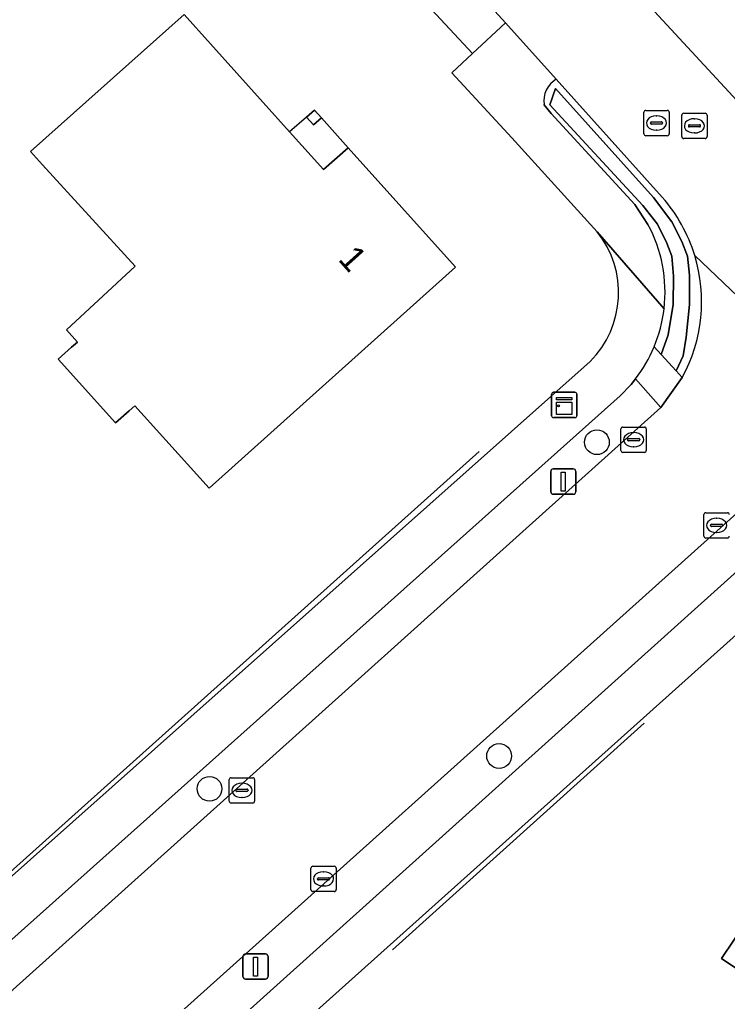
# Model space of a CAD drawing. Extents: x 163266 to 164362, y 381528 to 382286.
# Drawn here: x 163972.57 to 164000.54, y 381715.24 to 381754.03 of the extents above; entities that cross this region are included whole.
import ezdxf

# ---------------------------------------------------------------- set-up
doc = ezdxf.new("R2010")
doc.units = 0
for name, color, linetype in [('IMGEO_Boom', 7, 'Continuous'), ('IMGEO_Erf', 7, 'Continuous'), ('IMGEO_Groenvoorziening', 7, 'Continuous'), ('IMGEO_Haag', 7, 'Continuous'), ('IMGEO_Hek', 7, 'Continuous'), ('IMGEO_Kast', 7, 'Continuous'), ('IMGEO_Kolk', 7, 'Continuous'), ('IMGEO_Lichtmast', 7, 'Continuous'), ('IMGEO_Pand', 7, 'Continuous'), ('IMGEO_Pand_nummerreeks', 7, 'Continuous'), ('IMGEO_Pand_overbouw', 7, 'Continuous'), ('IMGEO_Rijbaan_lokaal_open', 7, 'Continuous'), ('IMGEO_Rioolput', 7, 'Continuous'), ('IMGEO_Voetpad_halfverhard', 7, 'Continuous'), ('IMGEO_Voetpad_open', 7, 'Continuous')]:
    doc.layers.add(name, color=color, linetype=linetype)

msp = doc.modelspace()

# ---------------------------------------------------------------- linework, layer by layer
at = {"layer": 'IMGEO_Boom'}
for centre in [(163995.384, 381737.33), (163991.517, 381724.931), (163980.071, 381723.636)]:
    msp.add_circle(centre, 0.489, dxfattribs=at)
at = {"layer": 'IMGEO_Erf'}
for points in [[(163995.387, 381745.649), (163992.019, 381749.355), (163989.649, 381751.925), (163990.472, 381752.694), (163988.491, 381754.827), (163984.719, 381759.012), (163982.069, 381761.923), (163978.56, 381765.822), (163974.277, 381770.593), (163973.349, 381771.686), (163967.885, 381777.728), (163964.295, 381781.762), (163960.808, 381785.63), (163959.925, 381786.632), (163952.554, 381794.921), (163948.897, 381798.995), (163947.249, 381800.847), (163946.513, 381801.63), (163938.906, 381810.141)], [(163907.846, 381662.609), (163917.878, 381671.183), (163917.751, 381671.321), (163960.431, 381709.666), (163995.111, 381740.522)], [(164004.063, 381732.568), (163952.896, 381686.744)]]:
    msp.add_lwpolyline(points, dxfattribs=at)
for points in [[(163979.064, 381754.234), (163983.233, 381749.598), (163984.57, 381748.111), (163985.554, 381748.969), (163989.791, 381744.248), (163980.063, 381735.515), (163977.118, 381738.774), (163976.899, 381738.577), (163976.361, 381738.091), (163974.092, 381740.608), (163974.62, 381741.084), (163974.849, 381741.291), (163974.416, 381741.778), (163977.13, 381744.283), (163973.47, 381748.297), (163972.999, 381748.813)], [(163983.902, 381750.181), (163984.219, 381750.457), (163984.499, 381750.144), (163984.183, 381749.868)], [(164004.047, 381714.414), (164000.307, 381716.936), (164007.188, 381727.15), (164014.659, 381722.117), (164013.975, 381721.119), (164021.456, 381716.087), (164018.88, 381712.276), (164022.863, 381709.597), (164018.147, 381702.585), (164014.306, 381705.169), (164016.56, 381708.521), (164016.411, 381708.622), (164016.338, 381708.513), (164013.436, 381710.47), (164013.827, 381711.05), (164009.251, 381714.137), (164007.752, 381711.915)]]:
    msp.add_lwpolyline(points, close=True, dxfattribs=at)
msp.add_arc((163992.41, 381743.238), 3.831, 314.8412, 38.996, dxfattribs=at)
at = {"layer": 'IMGEO_Groenvoorziening'}
for points in [[(163997.969, 381747.012), (163993.771, 381751.675)], [(163993.518, 381750.663), (163993.75, 381751.311), (163997.623, 381747.001), (163998.341, 381746.036), (163998.74, 381745.26), (163998.96, 381744.688), (163999.044, 381743.932), (163999.044, 381742.778), (163998.918, 381741.476), (163998.792, 381740.742), (163998.511, 381740.158), (163998.759, 381739.889)], [(163993.292, 381750.672), (163993.58, 381750.326), (163996.882, 381746.726), (163997.397, 381745.94)], [(163997.643, 381741.098), (163997.921, 381740.797), (163998.205, 381741.581), (163998.393, 381742.778), (163998.414, 381743.89), (163998.351, 381744.688), (163998.152, 381745.191), (163997.774, 381745.947), (163997.204, 381746.68), (163993.518, 381750.663)]]:
    msp.add_lwpolyline(points, dxfattribs=at)
for points in [[(163993.75, 381751.311), (163993.518, 381750.663), (163997.204, 381746.68), (163997.774, 381745.947), (163998.152, 381745.191), (163998.351, 381744.688), (163998.414, 381743.89), (163998.393, 381742.778), (163998.205, 381741.581), (163997.921, 381740.797), (163998.511, 381740.158), (163998.792, 381740.742), (163998.918, 381741.476), (163999.044, 381742.778), (163999.044, 381743.932), (163998.96, 381744.688), (163998.74, 381745.26), (163998.341, 381746.036), (163997.623, 381747.001)], [(163997.915, 381738.698), (163996.909, 381739.831), (163996.732, 381739.613), (163996.309, 381739.168), (163942.506, 381691.118), (163941.316, 381690.061), (163942.403, 381688.848)], [(164000.815, 381732.134), (164002.462, 381733.6), (164001.298, 381734.874), (163976.894, 381712.972), (163978.377, 381711.96), (163980.105, 381713.523)]]:
    msp.add_lwpolyline(points, close=True, dxfattribs=at)
for centre, radius, start, end in [((163994.298, 381750.808), 1.015, 121.2647, 187.6801), ((163993.259, 381742.878), 6.266, 16.9941, 41.2714), ((163992.454, 381743.261), 5.623, 353.3104, 28.4556), ((163993.273, 381742.886), 6.251, 331.3545, 16.9679), ((163992.459, 381743.262), 5.618, 337.3467, 353.2971)]:
    msp.add_arc(centre, radius, start, end, dxfattribs=at)
at = {"layer": 'IMGEO_Haag'}
for points in [[(163993.75, 381751.311), (163993.518, 381750.663), (163997.204, 381746.68), (163997.774, 381745.947), (163998.152, 381745.191), (163998.351, 381744.688), (163998.414, 381743.89), (163998.393, 381742.778), (163998.205, 381741.581), (163997.921, 381740.797), (163998.511, 381740.158), (163998.792, 381740.742), (163998.918, 381741.476), (163999.044, 381742.778), (163999.044, 381743.932), (163998.96, 381744.688), (163998.74, 381745.26), (163998.341, 381746.036), (163997.623, 381747.001)], [(163997.915, 381738.698), (163996.909, 381739.831), (163996.732, 381739.613), (163996.309, 381739.168), (163942.506, 381691.118), (163941.316, 381690.061), (163942.403, 381688.848)], [(163980.105, 381713.523), (164000.815, 381732.134), (164002.462, 381733.6), (164001.298, 381734.874), (163976.894, 381712.972), (163978.377, 381711.96)]]:
    msp.add_lwpolyline(points, close=True, dxfattribs=at)
at = {"layer": 'IMGEO_Hek'}
for points in [[(163924.002, 381677.14), (163990.733, 381736.967)], [(163987.306, 381717.275), (163997.245, 381726.234)]]:
    msp.add_lwpolyline(points, dxfattribs=at)
at = {"layer": 'IMGEO_Kast'}
for p, q in [((163993.592, 381738.378), (163993.592, 381739.219)), ((163993.592, 381739.219), (163993.592, 381738.378)), ((163993.667, 381739.303), (163994.508, 381739.303)), ((163994.508, 381739.303), (163993.667, 381739.303)), ((163994.592, 381739.228), (163994.592, 381738.387)), ((163994.592, 381738.387), (163994.592, 381739.228)), ((163994.517, 381738.303), (163993.676, 381738.303)), ((163993.676, 381738.303), (163994.517, 381738.303))]:
    msp.add_line(p, q, dxfattribs=at)
for points in [[(163993.787, 381739.093), (163994.387, 381739.093), (163994.387, 381739.008), (163993.787, 381739.008), (163993.787, 381739.093)], [(163993.787, 381738.918), (163994.387, 381738.918), (163994.387, 381738.429), (163993.787, 381738.429), (163993.787, 381738.918)]]:
    msp.add_lwpolyline(points, dxfattribs=at)
msp.add_circle((163993.871, 381738.767), 0.0377, dxfattribs=at)
for centre, start, end in [((163993.67, 381739.225), 92.4484, 184.2845), ((163993.67, 381739.225), 92.4484, 184.2845), ((163994.514, 381739.225), 2.4484, 94.2845), ((163994.514, 381739.225), 2.4484, 94.2845), ((163993.67, 381738.381), 182.4484, 274.2845), ((163993.67, 381738.381), 182.4484, 274.2845), ((163994.514, 381738.381), 272.4484, 4.2845), ((163994.514, 381738.381), 272.4484, 4.2845)]:
    msp.add_arc(centre, 0.0779, start, end, dxfattribs=at)
at = {"layer": 'IMGEO_Kolk'}
for p, q in [((163996.335, 381737.004), (163996.335, 381737.856)), ((163996.41, 381737.93), (163997.262, 381737.93)), ((163997.336, 381737.856), (163997.336, 381737.004)), ((163996.594, 381737.424), (163996.594, 381737.436)), ((163997.032, 381737.387), (163996.634, 381737.387)), ((163996.637, 381737.473), (163997.035, 381737.473)), ((163996.823, 381737.71), (163996.848, 381737.71)), ((163997.078, 381737.436), (163997.078, 381737.424)), ((163996.846, 381737.15), (163996.821, 381737.15)), ((163997.262, 381736.93), (163996.41, 381736.93)), ((163999.613, 381733.618), (163999.613, 381734.47)), ((163999.688, 381734.544), (164000.54, 381734.544)), ((164000.101, 381734.324), (164000.126, 381734.324)), ((163999.872, 381734.038), (163999.872, 381734.05)), ((164000.31, 381734.001), (163999.912, 381734.001)), ((163999.915, 381734.087), (164000.313, 381734.087)), ((164000.356, 381734.05), (164000.356, 381734.038)), ((164000.54, 381733.544), (163999.688, 381733.544)), ((164000.124, 381733.764), (164000.099, 381733.764)), ((163980.852, 381723.147), (163980.852, 381723.999)), ((163980.927, 381724.073), (163981.779, 381724.073)), ((163981.34, 381723.853), (163981.365, 381723.853)), ((163981.853, 381723.999), (163981.853, 381723.147)), ((163981.111, 381723.567), (163981.111, 381723.579)), ((163981.549, 381723.53), (163981.151, 381723.53)), ((163981.154, 381723.616), (163981.552, 381723.616)), ((163981.595, 381723.579), (163981.595, 381723.567)), ((163981.779, 381723.073), (163980.927, 381723.073)), ((163981.363, 381723.293), (163981.338, 381723.293)), ((163984.076, 381719.651), (163984.076, 381720.503)), ((163984.151, 381720.577), (163985.003, 381720.577)), ((163984.564, 381720.357), (163984.589, 381720.357)), ((163985.077, 381720.503), (163985.077, 381719.651)), ((163984.335, 381720.071), (163984.335, 381720.083)), ((163984.773, 381720.034), (163984.375, 381720.034)), ((163984.378, 381720.12), (163984.776, 381720.12)), ((163984.819, 381720.083), (163984.819, 381720.071)), ((163985.003, 381719.577), (163984.151, 381719.577)), ((163984.587, 381719.797), (163984.562, 381719.797))]:
    msp.add_line(p, q, dxfattribs=at)
for points in [[(163996.335, 381737.004), (163996.335, 381737.856)], [(163996.41, 381737.93), (163997.262, 381737.93)], [(163997.336, 381737.856), (163997.336, 381737.004)], [(163997.262, 381736.93), (163996.41, 381736.93)], [(163999.613, 381733.618), (163999.613, 381734.47)], [(163999.688, 381734.544), (164000.54, 381734.544)], [(164000.54, 381733.544), (163999.688, 381733.544)], [(163980.852, 381723.147), (163980.852, 381723.999)], [(163980.927, 381724.073), (163981.779, 381724.073)], [(163981.853, 381723.999), (163981.853, 381723.147)], [(163981.779, 381723.073), (163980.927, 381723.073)], [(163984.076, 381719.651), (163984.076, 381720.503)], [(163984.151, 381720.577), (163985.003, 381720.577)], [(163985.077, 381720.503), (163985.077, 381719.651)], [(163985.003, 381719.577), (163984.151, 381719.577)]]:
    msp.add_lwpolyline(points, dxfattribs=at)
for centre, radius, start, end in [((163996.412, 381737.854), 0.0765, 91.552, 178.448), ((163996.412, 381737.854), 0.0765, 91.552, 178.448), ((163997.26, 381737.854), 0.0765, 1.552, 88.448), ((163997.26, 381737.854), 0.0765, 1.552, 88.448), ((163996.634, 381737.433), 0.0403, 85.8775, 175.7526), ((163996.631, 381737.423), 0.0366, 178.938, 274.7102), ((163997.035, 381737.43), 0.043, 264.8664, 352.4533), ((163997.039, 381737.435), 0.0386, 1.7309, 96.639), ((163996.412, 381737.006), 0.0765, 181.552, 268.448), ((163996.412, 381737.006), 0.0765, 181.552, 268.448), ((163997.26, 381737.006), 0.0765, 271.552, 358.448), ((163997.26, 381737.006), 0.0765, 271.552, 358.448), ((163999.69, 381734.468), 0.0765, 91.552, 178.448), ((163999.69, 381734.468), 0.0765, 91.552, 178.448), ((164000.538, 381734.468), 0.0765, 1.552, 88.448), ((164000.538, 381734.468), 0.0765, 1.552, 88.448), ((163999.912, 381734.047), 0.0403, 85.8775, 175.7526), ((163999.909, 381734.037), 0.0366, 178.938, 274.7102), ((164000.313, 381734.044), 0.043, 264.8664, 352.4533), ((164000.317, 381734.049), 0.0386, 1.7309, 96.639), ((163999.69, 381733.62), 0.0765, 181.552, 268.448), ((163999.69, 381733.62), 0.0765, 181.552, 268.448), ((164000.538, 381733.62), 0.0765, 271.552, 358.448), ((164000.538, 381733.62), 0.0765, 271.552, 358.448), ((163980.929, 381723.997), 0.0765, 91.552, 178.448), ((163980.929, 381723.997), 0.0765, 91.552, 178.448), ((163981.777, 381723.997), 0.0765, 1.552, 88.448), ((163981.777, 381723.997), 0.0765, 1.552, 88.448), ((163981.151, 381723.576), 0.0403, 85.8775, 175.7526), ((163981.148, 381723.566), 0.0366, 178.938, 274.7102), ((163981.552, 381723.573), 0.043, 264.8664, 352.4533), ((163981.556, 381723.578), 0.0386, 1.7309, 96.639), ((163980.929, 381723.149), 0.0765, 181.552, 268.448), ((163980.929, 381723.149), 0.0765, 181.552, 268.448), ((163981.777, 381723.149), 0.0765, 271.552, 358.448), ((163981.777, 381723.149), 0.0765, 271.552, 358.448), ((163984.153, 381720.501), 0.0765, 91.552, 178.448), ((163984.153, 381720.501), 0.0765, 91.552, 178.448), ((163985.001, 381720.501), 0.0765, 1.552, 88.448), ((163985.001, 381720.501), 0.0765, 1.552, 88.448), ((163984.375, 381720.08), 0.0403, 85.8775, 175.7526), ((163984.372, 381720.07), 0.0366, 178.938, 274.7102), ((163984.776, 381720.077), 0.043, 264.8664, 352.4533), ((163984.78, 381720.082), 0.0386, 1.7309, 96.639), ((163984.153, 381719.653), 0.0765, 181.552, 268.448), ((163984.153, 381719.653), 0.0765, 181.552, 268.448), ((163985.001, 381719.653), 0.0765, 271.552, 358.448), ((163985.001, 381719.653), 0.0765, 271.552, 358.448)]:
    msp.add_arc(centre, radius, start, end, dxfattribs=at)
for centre, major_axis, ratio, start_param, end_param in [((163996.822, 381737.43), (-0.387, 0.002), 0.722429, 4.712389, 7.853982), ((163996.847, 381737.43), (-0.39, 0.002), 0.717154, 1.570796, 4.712389), ((164000.1, 381734.044), (-0.387, 0.002), 0.722429, 4.712389, 7.853982), ((164000.125, 381734.044), (-0.39, 0.002), 0.717154, 1.570796, 4.712389), ((163981.339, 381723.573), (-0.387, 0.002), 0.722429, 4.712389, 7.853982), ((163981.364, 381723.573), (-0.39, 0.002), 0.717154, 1.570796, 4.712389), ((163984.563, 381720.077), (-0.387, 0.002), 0.722429, 4.712389, 7.853982), ((163984.588, 381720.077), (-0.39, 0.002), 0.717154, 1.570796, 4.712389)]:
    msp.add_ellipse(centre, major_axis=major_axis, ratio=ratio, start_param=start_param, end_param=end_param, dxfattribs=at)
at = {"layer": 'IMGEO_Lichtmast'}
for p, q in [((163993.657, 381736.277), (163994.447, 381736.277)), ((163994.447, 381736.277), (163993.657, 381736.277)), ((163993.557, 381735.377), (163993.557, 381736.177)), ((163993.557, 381736.177), (163993.557, 381735.377)), ((163994.547, 381736.177), (163994.547, 381735.377)), ((163994.547, 381735.377), (163994.547, 381736.177)), ((163994.447, 381735.277), (163993.657, 381735.277)), ((163993.657, 381735.277), (163994.447, 381735.277)), ((163981.394, 381716.213), (163981.394, 381717.013)), ((163981.394, 381717.013), (163981.394, 381716.213)), ((163981.494, 381717.113), (163982.284, 381717.113)), ((163982.284, 381717.113), (163981.494, 381717.113)), ((163982.384, 381717.013), (163982.384, 381716.213)), ((163982.384, 381716.213), (163982.384, 381717.013)), ((163982.284, 381716.113), (163981.494, 381716.113)), ((163981.494, 381716.113), (163982.284, 381716.113))]:
    msp.add_line(p, q, dxfattribs=at)
for points in [[(163993.977, 381736.152), (163994.127, 381736.152), (163994.127, 381735.402), (163993.977, 381735.402), (163993.977, 381736.152)], [(163981.814, 381716.988), (163981.964, 381716.988), (163981.964, 381716.238), (163981.814, 381716.238), (163981.814, 381716.988)]]:
    msp.add_lwpolyline(points, dxfattribs=at)
for centre, start, end in [((163993.657, 381736.177), 90, 180), ((163993.657, 381736.177), 90, 180), ((163994.447, 381736.177), 0, 90), ((163994.447, 381736.177), 360, 90), ((163993.657, 381735.377), 180, 270), ((163993.657, 381735.377), 180, 270), ((163994.447, 381735.377), 270, 0), ((163994.447, 381735.377), 270, 0), ((163981.494, 381717.013), 90, 180), ((163981.494, 381717.013), 90, 180), ((163982.284, 381717.013), 0, 90), ((163982.284, 381717.013), 360, 90), ((163981.494, 381716.213), 180, 270), ((163981.494, 381716.213), 180, 270), ((163982.284, 381716.213), 270, 0), ((163982.284, 381716.213), 270, 0)]:
    msp.add_arc(centre, 0.1, start, end, dxfattribs=at)
at = {"layer": 'IMGEO_Pand'}
for points in [[(163985.554, 381748.969), (163984.57, 381748.111), (163983.233, 381749.598), (163979.064, 381754.234), (163972.999, 381748.813), (163973.47, 381748.297), (163977.13, 381744.283), (163974.416, 381741.778), (163974.849, 381741.291), (163974.62, 381741.084), (163974.092, 381740.608), (163976.361, 381738.091), (163976.899, 381738.577), (163977.118, 381738.774), (163980.063, 381735.515), (163989.791, 381744.248)], [(163983.902, 381750.181), (163984.183, 381749.868), (163984.499, 381750.144), (163984.219, 381750.457)], [(164007.752, 381711.915), (164009.251, 381714.137), (164013.827, 381711.05), (164013.436, 381710.47), (164016.338, 381708.513), (164016.411, 381708.622), (164016.56, 381708.521), (164014.306, 381705.169), (164018.147, 381702.585), (164022.863, 381709.597), (164018.88, 381712.276), (164021.456, 381716.087), (164013.975, 381721.119), (164014.659, 381722.117), (164007.188, 381727.15), (164000.307, 381716.936), (164004.047, 381714.414)]]:
    msp.add_lwpolyline(points, close=True, dxfattribs=at)
at = {"layer": 'IMGEO_Pand_overbouw'}
msp.add_lwpolyline([(163984.499, 381750.144), (163984.183, 381749.868), (163983.902, 381750.181), (163983.233, 381749.598), (163984.57, 381748.111), (163985.554, 381748.969)], close=True, dxfattribs=at)
at = {"layer": 'IMGEO_Rijbaan_lokaal_open'}
for points in [[(163940.175, 381811.378), (163947.882, 381802.848), (163948.608, 381802.051), (163949.93, 381800.54), (163954.145, 381795.79), (163961.321, 381787.863), (163962.215, 381786.818), (163965.351, 381783.35), (163969.517, 381778.666), (163974.718, 381772.924), (163975.687, 381771.828), (163979.634, 381767.455), (163983.813, 381762.764), (163985.255, 381761.132), (163985.739, 381760.594), (163990.087, 381755.766), (163991.765, 381753.902), (163993.771, 381751.675), (163997.969, 381747.012)], [(163994.884, 381757.372), (164005.983, 381745.357)], [(164009.357, 381741.672), (164005.983, 381745.357), (163994.884, 381757.372)], [(164008.6, 381735.726), (164008.883, 381735.535), (163999.252, 381744.71)], [(163999.252, 381744.71), (164008.883, 381735.535), (164016.853, 381730.156), (164018.052, 381729.344), (164026.521, 381723.615), (164031.695, 381720.116), (164032.207, 381719.769), (164040.374, 381714.295), (164041.569, 381713.485), (164044.956, 381711.196), (164050.355, 381707.539), (164058.116, 381702.356), (164059.338, 381701.54), (164063.682, 381698.622), (164068.515, 381695.376), (164069.911, 381694.44), (164075.422, 381690.725), (164080.018, 381687.656), (164081.239, 381686.855), (164087.153, 381682.87)], [(163998.759, 381739.889), (163997.915, 381738.698), (163942.403, 381688.848), (163941.352, 381687.896), (163927.758, 381675.613), (163931.115, 381671.809), (163939.045, 381678.955), (163939.273, 381679.115), (163939.322, 381679.159), (163950.08, 381688.697)], [(163973.846, 381710.232), (163975.86, 381712.042), (163976.894, 381712.972), (164001.298, 381734.874), (164002.467, 381735.733)]]:
    msp.add_lwpolyline(points, dxfattribs=at)
for centre, radius, start, end in [((163993.259, 381742.878), 6.266, 16.9941, 41.2714), ((163993.273, 381742.886), 6.251, 331.3545, 16.9679)]:
    msp.add_arc(centre, radius, start, end, dxfattribs=at)
at = {"layer": 'IMGEO_Rioolput'}
for p, q in [((163997.238, 381749.518), (163997.238, 381750.37)), ((163997.313, 381750.444), (163998.165, 381750.444)), ((163997.726, 381750.224), (163997.751, 381750.224)), ((163998.239, 381750.37), (163998.239, 381749.518)), ((163998.739, 381749.407), (163998.739, 381750.259)), ((163998.814, 381750.333), (163999.666, 381750.333)), ((163999.74, 381750.259), (163999.74, 381749.407)), ((163997.497, 381749.938), (163997.497, 381749.95)), ((163997.935, 381749.901), (163997.537, 381749.901)), ((163997.54, 381749.987), (163997.938, 381749.987)), ((163997.981, 381749.95), (163997.981, 381749.938)), ((163998.998, 381749.827), (163998.998, 381749.839)), ((163999.041, 381749.876), (163999.439, 381749.876)), ((163999.227, 381750.113), (163999.252, 381750.113)), ((163999.482, 381749.839), (163999.482, 381749.827)), ((163998.165, 381749.444), (163997.313, 381749.444)), ((163997.749, 381749.664), (163997.724, 381749.664)), ((163999.436, 381749.79), (163999.038, 381749.79)), ((163999.25, 381749.553), (163999.225, 381749.553)), ((163999.666, 381749.333), (163998.814, 381749.333))]:
    msp.add_line(p, q, dxfattribs=at)
for points in [[(163997.238, 381749.518), (163997.238, 381750.37)], [(163997.313, 381750.444), (163998.165, 381750.444)], [(163998.239, 381750.37), (163998.239, 381749.518)], [(163998.739, 381749.407), (163998.739, 381750.259)], [(163998.814, 381750.333), (163999.666, 381750.333)], [(163999.74, 381750.259), (163999.74, 381749.407)], [(163998.165, 381749.444), (163997.313, 381749.444)], [(163999.666, 381749.333), (163998.814, 381749.333)]]:
    msp.add_lwpolyline(points, dxfattribs=at)
for centre, radius, start, end in [((163997.315, 381750.368), 0.0765, 91.552, 178.448), ((163997.315, 381750.368), 0.0765, 91.552, 178.448), ((163998.163, 381750.368), 0.0765, 1.552, 88.448), ((163998.163, 381750.368), 0.0765, 1.552, 88.448), ((163998.816, 381750.257), 0.0765, 91.552, 178.448), ((163998.816, 381750.257), 0.0765, 91.552, 178.448), ((163999.664, 381750.257), 0.0765, 1.552, 88.448), ((163999.664, 381750.257), 0.0765, 1.552, 88.448), ((163997.537, 381749.947), 0.0403, 85.8775, 175.7526), ((163997.534, 381749.937), 0.0366, 178.938, 274.7102), ((163997.938, 381749.944), 0.043, 264.8664, 352.4533), ((163997.942, 381749.949), 0.0386, 1.7309, 96.639), ((163999.038, 381749.836), 0.0403, 85.8775, 175.7526), ((163999.035, 381749.826), 0.0366, 178.938, 274.7102), ((163999.439, 381749.833), 0.043, 264.8664, 352.4533), ((163999.443, 381749.838), 0.0386, 1.7309, 96.639), ((163997.315, 381749.52), 0.0765, 181.552, 268.448), ((163997.315, 381749.52), 0.0765, 181.552, 268.448), ((163998.163, 381749.52), 0.0765, 271.552, 358.448), ((163998.163, 381749.52), 0.0765, 271.552, 358.448), ((163998.816, 381749.409), 0.0765, 181.552, 268.448), ((163998.816, 381749.409), 0.0765, 181.552, 268.448), ((163999.664, 381749.409), 0.0765, 271.552, 358.448), ((163999.664, 381749.409), 0.0765, 271.552, 358.448)]:
    msp.add_arc(centre, radius, start, end, dxfattribs=at)
for centre, major_axis, ratio, start_param, end_param in [((163997.725, 381749.944), (-0.387, 0.002), 0.722429, 4.712389, 7.853982), ((163997.75, 381749.944), (-0.39, 0.002), 0.717154, 1.570796, 4.712389), ((163999.226, 381749.833), (-0.387, 0.002), 0.722429, 4.712389, 7.853982), ((163999.251, 381749.833), (-0.39, 0.002), 0.717154, 1.570796, 4.712389)]:
    msp.add_ellipse(centre, major_axis=major_axis, ratio=ratio, start_param=start_param, end_param=end_param, dxfattribs=at)
at = {"layer": 'IMGEO_Voetpad_halfverhard'}
msp.add_lwpolyline([(163991.765, 381753.902), (163990.087, 381755.766), (163989.204, 381755.509), (163988.491, 381754.827), (163990.472, 381752.694)], close=True, dxfattribs=at)
at = {"layer": 'IMGEO_Voetpad_open'}
for points in [[(163993.771, 381751.675), (163991.765, 381753.902), (163990.472, 381752.694), (163989.649, 381751.925), (163992.019, 381749.355), (163995.387, 381745.649), (163998.038, 381742.606)], [(163997.397, 381745.94), (163996.882, 381746.726), (163993.58, 381750.326), (163993.292, 381750.672)], [(163998.038, 381742.606), (163995.387, 381745.649)], [(163998.511, 381740.158), (163997.921, 381740.797), (163997.643, 381741.098)], [(163995.111, 381740.522), (163960.431, 381709.666), (163917.751, 381671.321), (163917.878, 381671.183), (163907.846, 381662.609)], [(163996.909, 381739.831), (163997.915, 381738.698), (163998.759, 381739.889), (163998.511, 381740.158)], [(163938.9, 381687.899), (163940.274, 381689.098), (163941.352, 381687.896), (163942.403, 381688.848), (163941.316, 381690.061), (163942.506, 381691.118), (163996.309, 381739.168), (163996.732, 381739.613), (163996.909, 381739.831)], [(164002.959, 381733.983), (164002.462, 381733.6), (164000.815, 381732.134), (163980.105, 381713.523), (163978.377, 381711.96), (163976.894, 381712.972), (163975.86, 381712.042), (163977.34, 381711.03), (163974.445, 381708.442), (163970.557, 381704.984), (163969.011, 381703.561), (163965.655, 381700.603), (163961.653, 381696.958), (163960.423, 381695.845), (163958.939, 381696.837), (163958.169, 381696.144), (163959.605, 381695.159), (163957.577, 381693.337), (163949.05, 381685.722)], [(163952.896, 381686.744), (164004.063, 381732.568)]]:
    msp.add_lwpolyline(points, dxfattribs=at)
for centre, radius, start, end in [((163994.298, 381750.808), 1.015, 121.2647, 187.6801), ((163992.454, 381743.261), 5.623, 353.3104, 28.4556), ((163992.41, 381743.238), 3.831, 314.8412, 38.996), ((163992.459, 381743.262), 5.618, 337.3467, 353.2971), ((163992.528, 381743.215), 5.536, 322.3161, 337.5147), ((163992.528, 381743.215), 5.536, 322.3161, 337.5147)]:
    msp.add_arc(centre, radius, start, end, dxfattribs=at)

# ---------------------------------------------------------------- texts
at = {"layer": 'IMGEO_Pand_nummerreeks'}
msp.add_text('1', height=1, rotation=311.9059, dxfattribs=at).set_placement((163985.123, 381744.538))

doc.saveas('drawing.dxf')
